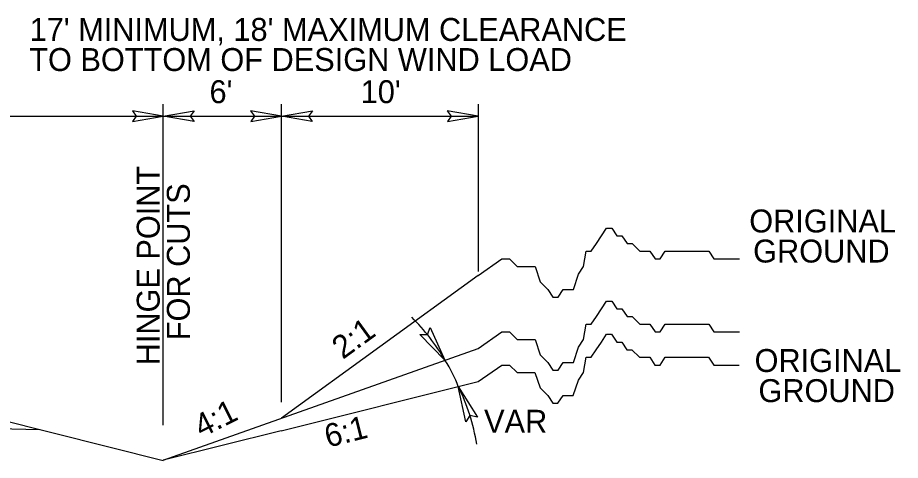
# Model space of a CAD drawing. Extents: x 1726582 to 1728895, y 538986 to 541550.
# Drawn here: x 1727891.1 to 1728160.3, y 541295.4 to 541430.6 of the extents above; entities that cross this region are included whole.
import ezdxf

# ---------------------------------------------------------------- set-up
doc = ezdxf.new("R2010")
doc.units = 0
for name, color, linetype in [('Default', 7, 'Continuous'), ('GSExisting', 7, 'Continuous'), ('GSRelocate', 7, 'Continuous'), ('GSReplace', 7, 'Continuous')]:
    doc.layers.add(name, color=color, linetype=linetype)

msp = doc.modelspace()

# ---------------------------------------------------------------- linework, layer by layer
at = {"layer": 'Default'}
for p, q in [((1727935.5, 541306.16), (1727935.5, 541404.16)), ((1727971.53, 541313.2), (1727971.53, 541404.16)), ((1728031.58, 541353.09), (1728031.58, 541404.16)), ((1727827.38, 541400.46), (1727935.46, 541400.46)), ((1727935.46, 541400.46), (1727971.49, 541400.46)), ((1727971.49, 541400.46), (1728031.54, 541400.46))]:
    msp.add_line(p, q, dxfattribs=at)
for points in [[(1727926.12, 541398.85), (1727935.5, 541400.47), (1727926.07, 541402.14), (1727927.27, 541400.47)], [(1727944.88, 541398.85), (1727935.5, 541400.47), (1727944.93, 541402.14), (1727943.73, 541400.47)], [(1727962.15, 541398.85), (1727971.53, 541400.47), (1727962.1, 541402.14), (1727963.3, 541400.47)], [(1727980.91, 541398.85), (1727971.53, 541400.47), (1727980.96, 541402.14), (1727979.76, 541400.47)], [(1728022.16, 541398.85), (1728031.54, 541400.46), (1728022.11, 541402.13), (1728023.31, 541400.46)], [(1728016.86, 541335.98), (1728021.41, 541326), (1728013.7, 541333.9), (1728016.07, 541333.84)], [(1728027.78, 541307.25), (1728025.45, 541317.96), (1728031.31, 541308.61), (1728029.01, 541309.17)], [(1728027.78, 541307.25), (1728025.45, 541317.96), (1728031.31, 541308.61), (1728029.01, 541309.17)]]:
    msp.add_lwpolyline(points, close=True, dxfattribs=at)
at = {"layer": 'GSExisting'}
for points in [[(1728031.54, 541351.91), (1728038.76, 541356.98), (1728041.1, 541356.98), (1728043.43, 541354.65), (1728044.99, 541354.65), (1728047.33, 541354.65), (1728048.88, 541354.65), (1728050.44, 541349.96), (1728052.78, 541347.64), (1728054.34, 541345.29), (1728055.89, 541345.29), (1728057.45, 541347.64), (1728059.01, 541347.64), (1728060.56, 541347.64), (1728062.12, 541352.31), (1728063.68, 541354.65), (1728064.46, 541359.32), (1728066.02, 541359.32), (1728067.58, 541361.65), (1728069.13, 541364), (1728070.69, 541366.34), (1728072.25, 541366.34), (1728073.8, 541364), (1728075.36, 541364), (1728076.92, 541361.65), (1728078.48, 541361.65), (1728080.82, 541359.32), (1728082.37, 541359.32), (1728083.93, 541359.32), (1728085.49, 541356.98), (1728087.04, 541356.98), (1728088.6, 541359.32), (1728090.16, 541359.32), (1728091.72, 541359.32), (1728093.27, 541359.32), (1728094.83, 541359.32), (1728097.17, 541359.32), (1728099.5, 541359.32), (1728101.84, 541359.32), (1728103.4, 541356.98), (1728105.73, 541356.98), (1728108.07, 541356.98), (1728111.18, 541356.98)], [(1728031.54, 541329.6), (1728038.76, 541334.67), (1728041.1, 541334.67), (1728043.43, 541332.34), (1728044.99, 541332.34), (1728047.33, 541332.34), (1728048.88, 541332.34), (1728050.44, 541327.65), (1728052.78, 541325.32), (1728054.34, 541322.98), (1728055.89, 541322.98), (1728057.45, 541325.32), (1728059.01, 541325.32), (1728060.56, 541325.32), (1728062.12, 541330), (1728063.68, 541332.34), (1728064.46, 541337.01), (1728066.02, 541337.01), (1728067.58, 541339.34), (1728069.13, 541341.68), (1728070.69, 541344.03), (1728072.25, 541344.03), (1728073.8, 541341.68), (1728075.36, 541341.68), (1728076.92, 541339.34), (1728078.48, 541339.34), (1728080.82, 541337.01), (1728082.37, 541337.01), (1728083.93, 541337.01), (1728085.49, 541334.67), (1728087.04, 541334.67), (1728088.6, 541337.01), (1728090.16, 541337.01), (1728091.72, 541337.01), (1728093.27, 541337.01), (1728094.83, 541337.01), (1728097.17, 541337.01), (1728099.5, 541337.01), (1728101.84, 541337.01), (1728103.4, 541334.67), (1728105.73, 541334.67), (1728108.07, 541334.67), (1728111.18, 541334.67)], [(1728031.51, 541319.48), (1728038.72, 541324.54), (1728041.06, 541324.54), (1728043.4, 541322.22), (1728044.95, 541322.22), (1728047.29, 541322.22), (1728048.85, 541322.22), (1728050.41, 541317.53), (1728052.75, 541315.2), (1728054.3, 541312.86), (1728055.86, 541312.86), (1728057.42, 541315.2), (1728058.98, 541315.2), (1728060.53, 541315.2), (1728062.09, 541319.87), (1728063.65, 541322.22), (1728064.43, 541326.89), (1728065.99, 541326.89), (1728067.54, 541329.22), (1728069.1, 541331.56), (1728070.66, 541333.91), (1728072.21, 541333.91), (1728073.77, 541331.56), (1728075.33, 541331.56), (1728076.89, 541329.22), (1728078.44, 541329.22), (1728080.78, 541326.89), (1728082.34, 541326.89), (1728083.9, 541326.89), (1728085.45, 541324.54), (1728087.01, 541324.54), (1728088.57, 541326.89), (1728090.13, 541326.89), (1728091.68, 541326.89), (1728093.24, 541326.89), (1728094.8, 541326.89), (1728097.14, 541326.89), (1728099.47, 541326.89), (1728101.81, 541326.89), (1728103.37, 541324.54), (1728105.7, 541324.54), (1728108.04, 541324.54), (1728111.15, 541324.54)]]:
    msp.add_lwpolyline(points, dxfattribs=at)
for centre, start, end in [((1727969.01, 541296.05), 29.7519, 45.5036), ((1727971.47, 541290.97), 8.9538, 26.5701), ((1727971.47, 541290.97), 8.9538, 26.5701)]:
    msp.add_arc(centre, 60.35, start, end, dxfattribs=at)
msp.add_ellipse((1727970.92, 541329.03), major_axis=(54.47, -25.99), ratio=0.5, start_param=0.463735, end_param=0.681536, dxfattribs=at)
at = {"layer": 'GSReplace'}
for p, q in [((1728031.54, 541351.91), (1727971.57, 541308.29)), ((1727935.45, 541295.46), (1728031.54, 541329.6)), ((1727827.39, 541322.46), (1727935.46, 541295.44)), ((1727971.47, 541304.47), (1728031.51, 541319.48)), ((1727898, 541304.81), (1727695.28, 541308.86)), ((1727971.47, 541304.47), (1727935.45, 541295.46))]:
    msp.add_line(p, q, dxfattribs=at)

# ---------------------------------------------------------------- texts
at = {"layer": 'GSRelocate'}
for s, height, p in [("17' MINIMUM, 18' MAXIMUM CLEARANCE", 7.0055, (1727894.73, 541423.45)), ('TO BOTTOM OF DESIGN WIND LOAD', 7.0055, (1727894.62, 541414.27)), ("6'", 7.005, (1727949.6, 541404.46)), ("10'", 7.005, (1727995.7, 541404.46)), ('ORIGINAL', 7.005, (1728114.2, 541365)), ('GROUND', 7.005, (1728115.38, 541355.82)), ('ORIGINAL', 7.005, (1728115.82, 541322.41)), ('GROUND', 7.005, (1728117, 541313.22)), ('VAR', 7.005, (1728033.34, 541303.86))]:
    msp.add_text(s, height=height, dxfattribs=at).set_placement(p)
for s, height, rotation, p in [('HINGE POINT', 7.0055, 90, (1727934.41, 541324.44)), ('FOR CUTS', 7.005, 90, (1727943.6, 541332.11)), ('2:1', 7.005, 36.0298, (1727990.25, 541326.09)), ('4:1', 7.005, 26.5701, (1727947.17, 541302.25)), ('6:1', 7.005, 14.0381, (1727985.68, 541299.31))]:
    msp.add_text(s, height=height, rotation=rotation, dxfattribs=at).set_placement(p)

doc.saveas('drawing.dxf')
